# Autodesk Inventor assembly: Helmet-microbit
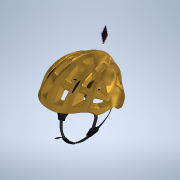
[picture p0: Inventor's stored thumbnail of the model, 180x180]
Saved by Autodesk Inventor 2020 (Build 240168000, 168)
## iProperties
Created: 2021-04
Part Number: Helmet-microbit
Document SubType Name: Assembly
Designer: bruno
Sending System: Autodesk Translation Framework v10.6.0.1341
Preprocessor: ST-DEVELOPER v18.1
Title: C:/Users/admin/Downloads/Ember Diamond bike Helmet.step
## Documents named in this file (6)
- C:\Users\bruno\Documents\1-Cours-2021-22\1STI2D\IT\Clignotant-casque\Inventor-casque\ember-diamond-bike-helmet-1.snapshot.1\Helmet-microbit.iam
- C:\Users\bruno\Documents\1-Cours-2021-22\1STI2D\IT\Clignotant-casque\Inventor-casque\ember-diamond-bike-helmet-1.snapshot.1\Helmet shell.ipt
- C:\Users\bruno\Documents\1-Cours-2021-22\1STI2D\IT\Clignotant-casque\Inventor-casque\ember-diamond-bike-helmet-1.snapshot.1\Strap.iam
- C:\Users\bruno\Documents\1-Cours-2021-22\1STI2D\IT\Clignotant-casque\Inventor-casque\ember-diamond-bike-helmet-1.snapshot.1\Strap holder Front.ipt
- C:\Users\bruno\Documents\1-Cours-2021-22\1STI2D\IT\Clignotant-casque\Inventor-casque\ember-diamond-bike-helmet-1.snapshot.1\Rear Lock.ipt
- C:\Users\bruno\Documents\1-Cours-2021-22\1STI2D\IT\Clignotant-casque\Inventor-casque\Micro-bit\microbit.ipt
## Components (5 placed, 5 different names)
1. Helmet shell:1
2. Strap:1 [sub-assembly]
3. Strap holder Front:2
4. Rear Lock:1
5. microbit:1
